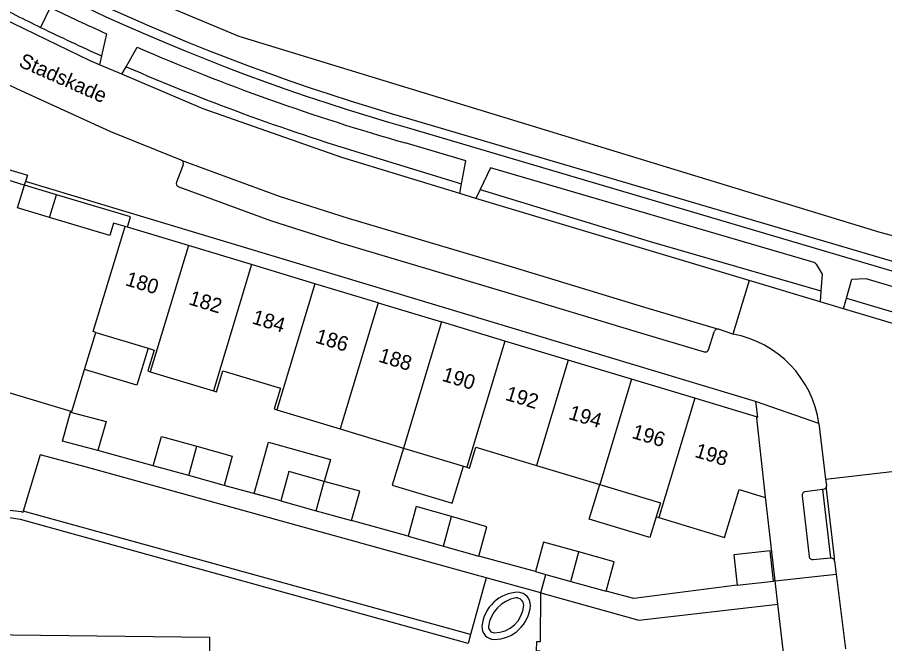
# Model space of a CAD drawing. Extents: x 194485 to 197793, y 468269 to 470822.
# Drawn here: x 194858.4 to 194929.3, y 469568.9 to 469620.1 of the extents above; entities that cross this region are included whole.
import ezdxf

# ---------------------------------------------------------------- set-up
doc = ezdxf.new("R2010")
doc.units = 0
for name, color, linetype in [('BGT begrenzing pand op maaiveld onder overbouw', 7, 'Continuous'), ('BGT grensvlak begroeid terreindeel LR', 7, 'Continuous'), ('BGT grensvlak gebouwinstallatie plus 1', 7, 'Continuous'), ('BGT grensvlak pand deel overbouw', 7, 'Continuous'), ('BGT grensvlak pand op maaiveld', 7, 'Continuous'), ('BGT grensvlak pand op maaiveld LR', 7, 'Continuous'), ('BGT grensvlak scheiding', 7, 'Continuous'), ('BGT grensvlak vegetatieobject', 7, 'Continuous'), ('BGT grensvlak waterdeel', 7, 'Continuous'), ('BGT grensvlak wegdeel', 7, 'Continuous'), ('BGT tekst huisnummerreeks', 7, 'Continuous'), ('BGT tekst openbare ruimte label weg', 7, 'Continuous')]:
    doc.layers.add(name, color=color, linetype=linetype)

msp = doc.modelspace()

# ---------------------------------------------------------------- linework, layer by layer
at = {"layer": 'BGT begrenzing pand op maaiveld onder overbouw'}
msp.add_lwpolyline([(194861.077, 469603.726), (194858.464, 469604.517), (194859.025, 469606.361)], dxfattribs=at)
at = {"layer": 'BGT grensvlak begroeid terreindeel LR'}
msp.add_line((194890.67, 469611.727), (194930.992, 469599.813), dxfattribs=at)
msp.add_arc((194938.674, 469780.461), 175.43, 235.78697, 254.11917, dxfattribs=at)
at = {"layer": 'BGT grensvlak gebouwinstallatie plus 1'}
for points in [[(194867.427, 469602.933), (194867.677, 469603.759), (194861.642, 469605.569)], [(194869.122, 469593.045), (194868.202, 469590.011), (194863.939, 469591.304)], [(194879.957, 469580.569), (194877.798, 469581.169), (194878.966, 469585.366), (194884.013, 469583.962), (194883.512, 469582.161)], [(194889.979, 469584.886), (194889.063, 469581.86), (194893.95, 469580.381), (194894.866, 469583.407)], [(194910.62, 469579.281), (194910.102, 469577.593), (194905.151, 469579.087), (194906.005, 469581.917)]]:
    msp.add_lwpolyline(points, dxfattribs=at)
at = {"layer": 'BGT grensvlak pand deel overbouw'}
for p, q in [((194861.642, 469605.569), (194859.025, 469606.361)), ((194861.077, 469603.726), (194861.642, 469605.569))]:
    msp.add_line(p, q, dxfattribs=at)
at = {"layer": 'BGT grensvlak pand op maaiveld'}
for p, q in [((194859.003, 469606.368), (194850.088, 469609.068)), ((194859.025, 469606.361), (194859.003, 469606.368)), ((194867.427, 469602.933), (194867.24, 469602.988)), ((194872.41, 469601.429), (194867.427, 469602.933)), ((194877.58, 469599.868), (194872.41, 469601.429)), ((194882.749, 469598.308), (194877.58, 469599.868)), ((194887.919, 469596.747), (194882.749, 469598.308)), ((194887.919, 469596.747), (194893.089, 469595.187)), ((194898.259, 469593.629), (194893.089, 469595.187)), ((194863.939, 469591.304), (194864.861, 469594.337)), ((194864.861, 469594.337), (194869.122, 469593.045)), ((194903.43, 469592.072), (194898.259, 469593.629)), ((194908.6, 469590.514), (194903.43, 469592.072)), ((194869.299, 469591.121), (194874.468, 469589.559)), ((194913.771, 469588.957), (194908.6, 469590.514)), ((194918.875, 469587.419), (194913.771, 469588.957)), ((194879.642, 469588.013), (194884.81, 469586.45)), ((194862.128, 469585.461), (194862.793, 469587.831)), ((194884.81, 469586.45), (194889.979, 469584.886)), ((194865.022, 469584.682), (194862.128, 469585.461)), ((194889.979, 469584.886), (194894.866, 469583.407)), ((194872.441, 469582.643), (194869.548, 469583.444)), ((194894.866, 469583.407), (194895.148, 469583.322)), ((194900.835, 469583.476), (194906.005, 469581.917)), ((194875.333, 469581.842), (194872.441, 469582.643)), ((194879.957, 469580.569), (194882.848, 469579.765)), ((194882.848, 469579.765), (194885.739, 469578.961)), ((194910.62, 469579.281), (194910.831, 469579.217)), ((194890.362, 469577.708), (194893.245, 469576.891)), ((194893.245, 469576.891), (194896.127, 469576.074)), ((194916.959, 469576.166), (194917.241, 469573.696)), ((194900.761, 469574.797), (194901.607, 469574.563)), ((194901.607, 469574.563), (194903.644, 469573.998)), ((194917.241, 469573.696), (194920.192, 469574.033))]:
    msp.add_line(p, q, dxfattribs=at)
for points in [[(194867.24, 469602.988), (194866.307, 469603.266), (194865.99, 469602.238), (194861.077, 469603.726)], [(194869.122, 469593.045), (194869.614, 469592.896), (194869.095, 469591.183), (194869.299, 469591.121)], [(194841.914, 469581.875), (194849.169, 469589.172), (194849.068, 469589.277), (194851.302, 469591.505), (194852.859, 469591.047), (194852.817, 469590.903), (194862.81, 469587.891)], [(194862.81, 469587.891), (194862.894, 469587.866), (194863.939, 469591.304)], [(194874.468, 469589.559), (194874.707, 469589.487), (194875.227, 469591.202), (194879.942, 469589.771), (194879.422, 469588.08), (194879.642, 469588.013)], [(194862.793, 469587.831), (194865.687, 469587.052), (194865.022, 469584.682)], [(194919.552, 469580.899), (194918.844, 469587.323), (194918.875, 469587.419)], [(194869.548, 469583.444), (194870.212, 469585.84), (194873.105, 469585.039)], [(194873.105, 469585.039), (194875.997, 469584.238), (194875.333, 469581.842)], [(194895.148, 469583.322), (194895.371, 469583.254), (194895.888, 469584.969), (194900.835, 469583.476)], [(194883.512, 469582.161), (194880.621, 469582.965), (194879.957, 469580.569)], [(194885.739, 469578.961), (194886.403, 469581.357), (194883.512, 469582.161)], [(194906.005, 469581.917), (194910.969, 469580.419), (194910.62, 469579.281)], [(194910.831, 469579.217), (194916.205, 469577.58), (194917.397, 469581.506), (194919.446, 469580.887), (194919.552, 469580.899)], [(194893.906, 469579.287), (194891.023, 469580.104), (194890.362, 469577.708)], [(194896.127, 469576.074), (194896.788, 469578.47), (194893.906, 469579.287)], [(194904.308, 469576.408), (194901.425, 469577.207), (194900.761, 469574.797)], [(194906.529, 469573.213), (194907.19, 469575.61), (194904.308, 469576.408)], [(194920.192, 469574.033), (194919.91, 469576.503), (194916.959, 469576.166)], [(194903.644, 469573.998), (194906.526, 469573.2), (194906.529, 469573.213)]]:
    msp.add_lwpolyline(points, dxfattribs=at)
at = {"layer": 'BGT grensvlak pand op maaiveld LR'}
for p, q in [((194872.41, 469601.429), (194869.299, 469591.121)), ((194877.58, 469599.868), (194874.468, 469589.559)), ((194882.749, 469598.308), (194879.642, 469588.013)), ((194887.919, 469596.747), (194884.81, 469586.45)), ((194893.089, 469595.187), (194889.979, 469584.886)), ((194898.259, 469593.629), (194895.148, 469583.322)), ((194903.43, 469592.072), (194900.835, 469583.476)), ((194908.6, 469590.514), (194906.005, 469581.917)), ((194913.771, 469588.957), (194910.831, 469579.217)), ((194872.441, 469582.643), (194873.105, 469585.039)), ((194882.848, 469579.765), (194883.512, 469582.161)), ((194893.245, 469576.891), (194893.906, 469579.287)), ((194903.644, 469573.998), (194904.308, 469576.408))]:
    msp.add_line(p, q, dxfattribs=at)
msp.add_lwpolyline([(194864.861, 469594.337), (194864.648, 469594.402), (194867.24, 469602.988)], dxfattribs=at)
at = {"layer": 'BGT grensvlak scheiding'}
msp.add_line((194859.102, 469606.66), (194859.003, 469606.368), dxfattribs=at)
msp.add_lwpolyline([(194846.382, 469611.036), (194859.273, 469607.169), (194859.102, 469606.66)], dxfattribs=at)
for centre, radius, start, end in [((194899.424, 469570.061), 3.051, 91.11778, 174.84183), ((194899.312, 469572.08), 1.032, 357.69698, 87.11057), ((194899.626, 469569.973), 2.723, 99.90607, 172.92), ((194899.181, 469572.039), 0.617, 2.55762, 92.10559), ((194897.383, 469572.23), 2.966, 269.66869, 356.30871), ((194897.395, 469572.211), 2.407, 269.88717, 356.5805), ((194897.4, 469570.28), 1.017, 176.90305, 268.07423), ((194897.404, 469570.284), 0.48, 177.03756, 268.36237)]:
    msp.add_arc(centre, radius, start, end, dxfattribs=at)
at = {"layer": 'BGT grensvlak vegetatieobject'}
for p, q in [((194886.711, 469608.917), (194894.718, 469606.465)), ((194926.155, 469597.117), (194950.975, 469589.85))]:
    msp.add_line(p, q, dxfattribs=at)
msp.add_lwpolyline([(194896.235, 469606.001), (194910.111, 469601.752), (194923.036, 469598.017), (194924.07, 469597.718)], dxfattribs=at)
for centre, radius, start, end in [((194939.502, 469782.263), 181.226, 244.10154, 245.83821), ((194938.642, 469780.412), 179.186, 246.54841, 253.15293)]:
    msp.add_arc(centre, radius, start, end, dxfattribs=at)
at = {"layer": 'BGT grensvlak waterdeel'}
msp.add_lwpolyline([(194822.494, 469649.692), (194848.181, 469632.596), (194861.722, 469624.726), (194876.54, 469618.509), (194928.873, 469602.517), (194938.02, 469600.088), (194982.982, 469586.61), (195000, 469581.494), (195006.376, 469579.649), (195060.365, 469563.684), (195090.937, 469553.27), (195126.606, 469536.49), (195154.352, 469519.31), (195167.226, 469509.857), (195177.122, 469501.144)], dxfattribs=at)
at = {"layer": 'BGT grensvlak wegdeel'}
for p, q in [((194861.138, 469620.87), (194860.347, 469619.238)), ((194865.728, 469618.72), (194865.324, 469616.914)), ((194867.331, 469616.028), (194868.24, 469617.611)), ((194865.324, 469616.914), (194865.161, 469616.185)), ((194866.978, 469615.414), (194865.161, 469616.185)), ((194866.978, 469615.414), (194867.331, 469616.028)), ((194890.457, 469611.008), (194929.855, 469599.368)), ((194895.069, 469608.356), (194890.115, 469609.806)), ((194871.991, 469608.01), (194871.449, 469606.6)), ((194894.718, 469606.465), (194895.069, 469608.356)), ((194897.083, 469607.767), (194896.235, 469606.001)), ((194923.527, 469600.029), (194897.083, 469607.767)), ((194918.734, 469588.68), (194859.102, 469606.66)), ((194894.571, 469605.675), (194894.718, 469606.465)), ((194895.886, 469605.275), (194894.571, 469605.675)), ((194896.235, 469606.001), (194895.886, 469605.275)), ((194918.221, 469598.576), (194895.886, 469605.275)), ((194923.673, 469599.916), (194924.16, 469599.098)), ((194924.16, 469599.098), (194924.07, 469597.718)), ((194926.155, 469597.117), (194926.587, 469598.677)), ((194926.587, 469598.677), (194927.742, 469598.743)), ((194918.221, 469598.576), (194916.883, 469594.199)), ((194924.013, 469596.839), (194918.221, 469598.576)), ((194924.07, 469597.718), (194924.013, 469596.839)), ((194925.92, 469596.269), (194924.013, 469596.839)), ((194925.92, 469596.269), (194926.155, 469597.117)), ((194914.893, 469592.909), (194915.336, 469594.383)), ((194916.883, 469594.199), (194915.704, 469594.585)), ((194923.907, 469586.905), (194918.734, 469588.68)), ((194918.734, 469588.68), (194918.875, 469587.419)), ((194862.793, 469587.831), (194862.81, 469587.891)), ((194923.907, 469586.905), (194924.453, 469582.344)), ((194869.548, 469583.444), (194865.022, 469584.682)), ((194924.453, 469582.344), (194929.861, 469582.986)), ((194924.453, 469582.344), (194924.513, 469581.839)), ((194879.957, 469580.569), (194875.333, 469581.842)), ((194924.509, 469581.741), (194924.473, 469581.65)), ((194924.515, 469581.798), (194924.509, 469581.741)), ((194924.513, 469581.839), (194924.515, 469581.798)), ((194920.333, 469574.048), (194919.552, 469580.899)), ((194922.525, 469580.991), (194923.098, 469576.047)), ((194924.2, 469581.499), (194922.789, 469581.326)), ((194924.25, 469581.505), (194924.2, 469581.499)), ((194924.2, 469581.499), (194924.843, 469575.92)), ((194924.324, 469581.524), (194924.25, 469581.505)), ((194924.4, 469581.567), (194924.324, 469581.524)), ((194895.458, 469569.655), (194858.924, 469579.738)), ((194890.362, 469577.708), (194885.739, 469578.961)), ((194900.761, 469574.797), (194896.127, 469576.074)), ((194923.43, 469575.779), (194924.843, 469575.92)), ((194924.843, 469575.92), (194924.911, 469575.922)), ((194924.911, 469575.922), (194924.978, 469575.907)), ((194924.978, 469575.907), (194925.033, 469575.883)), ((194925.033, 469575.883), (194925.089, 469575.84)), ((194925.089, 469575.84), (194925.132, 469575.79)), ((194925.132, 469575.79), (194925.154, 469575.75)), ((194925.154, 469575.75), (194925.179, 469575.663)), ((194925.179, 469575.663), (194925.312, 469574.594)), ((194901.19, 469573.059), (194901.607, 469574.563)), ((194920.333, 469574.048), (194925.312, 469574.594)), ((194925.312, 469574.594), (194926.072, 469568.507)), ((194896.737, 469574.29), (194895.458, 469569.655)), ((194901.19, 469573.059), (194896.737, 469574.29)), ((194920.333, 469574.048), (194920.192, 469574.033)), ((194920.538, 469572.135), (194920.333, 469574.048)), ((194921.027, 469567.954), (194920.538, 469572.135))]:
    msp.add_line(p, q, dxfattribs=at)
for points in [[(194865.161, 469616.185), (194864.393, 469616.51), (194854.48, 469621.309), (194844.007, 469627.113)], [(194871.82, 469608.4), (194866.079, 469610.723), (194858.749, 469614.054), (194857.899, 469614.473), (194849.329, 469618.847), (194841.203, 469623.455), (194840.4, 469623.933)], [(194894.571, 469605.675), (194884.932, 469608.603), (194873.616, 469612.6), (194866.978, 469615.414)], [(194871.82, 469608.4), (194879.813, 469605.469), (194885.449, 469603.656), (194898.867, 469599.678), (194909.664, 469596.399), (194915.704, 469594.585)], [(194871.624, 469606.218), (194879.125, 469603.469), (194884.824, 469601.635), (194898.259, 469597.652), (194909.055, 469594.374), (194914.53, 469592.746)], [(194927.742, 469598.743), (194945.195, 469593.56), (194950.699, 469591.925)], [(194937.702, 469592.749), (194937.68, 469592.756), (194925.92, 469596.269)], [(194896.737, 469574.29), (194864.088, 469583.33), (194860.314, 469584.336), (194858.924, 469579.738)], [(194925.179, 469575.663), (194925.187, 469575.951), (194924.529, 469581.521), (194924.515, 469581.798)], [(194858.924, 469579.738), (194858.88, 469579.64), (194858.791, 469579.674), (194857.303, 469579.857), (194857.189, 469579.908)], [(194895.458, 469569.655), (194895.254, 469568.934), (194858.699, 469579.053), (194857.003, 469579.291), (194850.878, 469579.454), (194837.05, 469565.59)], [(194917.241, 469573.696), (194908.785, 469572.591), (194906.529, 469573.213)], [(194901.107, 469565.787), (194901.143, 469568.316), (194900.853, 469568.332), (194900.87, 469569.105), (194901.155, 469569.106), (194901.19, 469573.059)], [(194901.19, 469573.059), (194909.189, 469570.849), (194920.538, 469572.135)], [(194848.741, 469565.139), (194848.814, 469569.737), (194874.137, 469569.444), (194874.071, 469564.849), (194848.741, 469565.139)]]:
    msp.add_lwpolyline(points, dxfattribs=at)
for centre, radius, start, end in [((194938.664, 469780.441), 176.158, 235.78585, 254.11783), ((194939.143, 469781.35), 180.247, 242.64463, 244.07747), ((194937.837, 469778.64), 175.426, 244.0734, 245.72891), ((194938.613, 469780.289), 177.247, 246.60702, 254.12018), ((194871.712, 469608.12), 0.3, 338.49581, 68.85539), ((194871.711, 469606.489), 0.285, 157.05109, 252.17538), ((194923.457, 469599.788), 0.251, 30.68503, 73.83719), ((194915.623, 469594.296), 0.3, 74.4049, 163.12102), ((194915.294, 469585.64), 8.705, 8.35527, 79.48409), ((194914.619, 469593.034), 0.301, 252.82922, 335.53436), ((194924.234, 469581.787), 0.275, 307.09194, 330.24363), ((194922.82, 469581.03), 0.298, 96.02012, 187.49944), ((194923.396, 469576.076), 0.299, 185.57225, 276.6048)]:
    msp.add_arc(centre, radius, start, end, dxfattribs=at)

# ---------------------------------------------------------------- texts
at = {"layer": 'BGT tekst huisnummerreeks'}
for s, p in [('180', (194867.197, 469598.197)), ('182', (194872.37, 469596.636)), ('184', (194877.536, 469595.077)), ('186', (194882.703, 469593.517)), ('188', (194887.872, 469591.956)), ('190', (194893.047, 469590.396)), ('192', (194898.222, 469588.837)), ('194', (194903.388, 469587.281)), ('196', (194908.557, 469585.724)), ('198', (194913.693, 469584.177))]:
    msp.add_text(s, height=1.2, rotation=343.2, dxfattribs=at).set_placement(p)
at = {"layer": 'BGT tekst openbare ruimte label weg'}
msp.add_text('Stadskade', height=1.2, rotation=336.3, dxfattribs=at).set_placement((194858.477, 469616.083))

doc.saveas('drawing.dxf')
